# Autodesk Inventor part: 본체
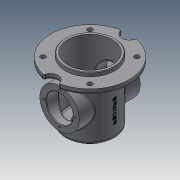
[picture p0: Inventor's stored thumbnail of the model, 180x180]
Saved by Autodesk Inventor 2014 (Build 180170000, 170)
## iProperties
Created: 2018-04
Part Number: 본체
Material: 일반
Document SubType Name: Modeling
Designer: NET
Density: 1 g/cm^3
Appearance: 기본값
Mass: 424.295 g
Surface Area: 1204.04 cm^2
Volume: 424.295 cm^3
Author: NET
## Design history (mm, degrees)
sketch "스케치1"
  geometry: C1 r 80 at (0, 0); 1 further point
  constraints: 1 centre point, 1 coincident
  dimensions: "d0" = 160 diameter of C1
extrude "돌출1" new body sketch "스케치1" distance "d1" = 10; taper "d2" = 0 deg
sketch "스케치2"
  geometry: C1 r 80 at (0, 0) reference; C2 r 50 at (0, 0)
  constraints: 1 centre point, 1 coincident
  dimensions: "d3" = 100 diameter of C2
extrude "돌출2" join sketch "스케치2" distance "d4" = 8; taper "d5" = 0 deg
sketch "스케치3"
  geometry: C1 r 80 at (0, 0) reference; C2 r 50 at (0, 0)
  constraints: 1 centre point, 1 coincident
  dimensions: "d6" = 100 diameter of C2
extrude "돌출3" join sketch "스케치3" distance "d7" = 110; taper "d8" = 0 deg
sketch "스케치4"
  geometry: C1 r 50 at (0, 0) reference; C2 r 40 at (0, 0)
  constraints: 1 centre point, 1 coincident
  dimensions: "d9" = 80 diameter of C2
extrude "돌출4" join sketch "스케치4" distance "d10" = 5; taper "d11" = 0 deg
node "작업 평면1"
sketch "스케치5"
  geometry: L1 (80, 10)-(-80, 10) reference; C1 r 40 at (0, -50); 1 further point
  constraints: 1 centre point, 1 vertical alignment
  dimensions: "d13" = 80 diameter of C1; "d14" = 60 distance from line of C1.centre L1
extrude "돌출5" join sketch "스케치5" stored distance "d15" = 5; taper "d16" = 0 deg
sketch "스케치6"
  geometry: C1 r 50 at (0, 0) reference; C2 r 45 at (0, 0)
  constraints: 1 centre point, 1 coincident
  dimensions: "d17" = 90 diameter of C2
extrude "돌출6" cut sketch "스케치6" distance "d18" = 120; taper "d19" = 0 deg
sketch "스케치7"
  geometry: C1 r 40 at (0, 0) reference; C2 r 27 at (0, 0); 1 further point
  constraints: 1 centre point, 1 coincident
  dimensions: "d20" = 54 diameter of C2
extrude "돌출7" cut sketch "스케치7" distance "d21" = 40; taper "d22" = 0 deg
sketch "스케치8" dims "d23" = 65
  geometry: C1 r 27 at (0, 0) reference; C2 r 40 at (0, 0) reference; C3 r 2 at (0, 32.5); 2 further points
  constraints: 2 vertical alignment, 1 centre point, 1 coincident, 2 other
  dimensions: "d24" = 4 diameter of C3
hole "구멍1" sketch "스케치8" at (0, 32.5) diameter "d25" = 3.242; stored, may be unused: countersink angle "d29" = 90 deg, drill point angle "d31" = 118 deg; dims "d26" = 8, "d27" = 4, "d28" = 2, "d30" = 10
sketch "스케치9"
  geometry: C1 r 40 at (0, 0) reference; C2 r 27 at (0, 0)
  constraints: 1 centre point, 1 coincident
  dimensions: "d35" = 54 diameter of C2
extrude "돌출8" cut sketch "스케치9" distance "d36" = 13; taper "d37" = 0 deg
sketch "스케치10" dims "d38" = 65
  geometry: C1 r 27 at (0, 0) reference; C2 r 40 at (0, 0) reference; C3 r 2 at (0, 32.5); 1 further point
  constraints: 2 vertical alignment, 1 centre point, 1 coincident, 2 other
  dimensions: "d39" = 4 diameter of C3
hole "구멍2" sketch "스케치10" at (0, 32.5) diameter "d40" = 3.242; stored, may be unused: countersink angle "d44" = 90 deg, drill point angle "d46" = 118 deg; dims "d41" = 8, "d42" = 4, "d43" = 2, "d45" = 10
sketch "스케치11" dims "d50" = 135
  geometry: L1 (0, 0)-(-71.606, 71.606); L2 (0, 0)-(0, 105.551); C1 r 80 at (0, 0) reference; C2 r 5 at (-47.73, 47.73)
  constraints: 4 end point, 1 centre point, 1 coincident, 1 point on line, 1 vertical, 3 other
  dimensions: "d51" = 45 deg angle of L1 L2; "d52" = 10 diameter of C2
extrude "돌출9" cut sketch "스케치11" distance "d53" = 10; taper "d54" = 0 deg
node "작업 평면2"
sketch "스케치12"
  geometry: C1 r 50 at (0, 0) reference; C2 r 15 at (0, 80); C3 r 15 at (0, -80); A1 r 80 centre (0, 0) between (0, 80) and (0, -80) reference; A2 r 80 centre (0, 0) between (0, 80) and (0, -80) reference
  constraints: 4 point on circle, 2 centre point, 2 vertical alignment
  dimensions: "d72" = 30 diameter of C2; "d73" = 30 diameter of C3
sketch "스케치13"
  geometry: L1 (0, 10)-(0, 10) reference; 2 further points
  constraints: 1 other
  dimensions: "d63" = 70 distance from line of L1 point (0, -60)
feature "엠보싱1" sketch "스케치13" dims "d64" = 0.5, "d65" = 0
chamfer "모따기1" distance "d66" = 1; stored, may be unused: second distance "d67" = 2, angle "d68" = 45 deg
fillet "모깎기1" dims "d69" = 5
fillet "모깎기2" dims "d70" = 3
fillet "모깎기3" dims "d71" = 3
extrude "돌출11" cut sketch "스케치12" distance "d74" = 10; taper "d75" = 0 deg
fillet "모깎기4" dims "d76" = 3
fillet "모깎기5" dims "d77" = 3
node "솔리드1"
mirror "대칭1"
pattern_circular "원형 패턴1" dims angle "d33" = 360 deg
mirror "대칭2"
pattern_circular "원형 패턴2" dims angle "d48" = 360 deg
pattern_circular "원형 패턴3" dims angle "d56" = 360 deg
other parameters: "d12" = 62
